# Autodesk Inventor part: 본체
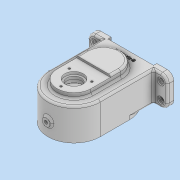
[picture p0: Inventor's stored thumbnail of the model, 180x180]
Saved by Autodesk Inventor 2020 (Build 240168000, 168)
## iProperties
Created: 2021-05
Part Number: 본체
Material: 일반
Document SubType Name: Modeling
Designer: Owner
Density: 1 g/cm^3
Appearance: 기본값
Mass: 280.11 g
Surface Area: 582.454 cm^2
Volume: 280.11 cm^3
Author: Owner
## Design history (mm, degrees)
sketch "스케치2"
  geometry: L1 (-61, 21.643)-(-35, 21.643); L2 (-35, 21.643)-(-35, -24.357); L3 (-35, -24.357)-(-61, -24.357); L4 (-61, -24.357)-(-61, 21.643); L5 (35, 21.643)-(61, 21.643); L6 (61, 21.643)-(61, -24.357); L7 (61, -24.357)-(35, -24.357); L8 (35, -24.357)-(35, 21.643); L9 (0, 30.578)-(0, 7.094); 1 further point
  constraints: 18 end point, 4 parallel, 2 horizontal, 2 perpendicular, 1 collinear, 1 point on line, 1 vertical, 2 other
  dimensions: "d2" = 46 distance of L1.end L2.end; "d3" = 46 distance of L7.end L5.start; "d4" = 122 distance between parallel lines of L6 L4; "d5" = 70 distance between parallel lines of L2 L8
extrude "돌출1" new body sketch "스케치2" distance "d6" = 10; taper "d7" = 0 deg
sketch "스케치3"
  geometry: L1 (-35, -92)-(-35, -47); L2 (5, -92)-(5, -47); L3 (-75, -47)-(-75, -92); L4 (-70, 0)-(-96, 0) reference; A1 r 40 centre (-35, -92) between (-75, -92) and (5, -92); A2 r 40 centre (-35, -47) between (5, -47) and (-75, -47); 2 further points
  constraints: 8 end point, 4 point on circle, 4 tangent, 2 centre point, 1 midpoint, 1 parallel, 1 vertical
  dimensions: "d8" = 80 distance between parallel lines of L2 L3; "d9" = 45 distance of L3.start L3.end; "d10" = 47 distance from line of L4 L3.start
extrude "돌출2" join sketch "스케치3" distance "d11" = 49; taper "d12" = 0 deg
sketch "스케치4"
  geometry: L1 (5, -92)-(5, -47) reference; L2 (5, -47)-(5, -10); L3 (0, -10)-(26, -10) reference; L4 (-75, -47)-(-75, -10); L5 (11.632, -5)-(-75, -5); L6 (26, 0)-(0, 0) reference; L7 (26, -10)-(0, -10) reference; L8 (0, 0)-(0, -10) reference; L9 (-70, 0)-(-70, -10) reference; L10 (-70, -10)-(-96, -10) reference; A1 r 40 centre (-35, -47) between (5, -47) and (-75, -47) reference; A2 r 40 centre (-35, -47) between (5, -47) and (-75, -47) reference; 3 further points
  constraints: 6 end point, 2 point on line, 2 vertical, 1 horizontal, 1 tangent
  dimensions: "d13" = 5 distance between parallel lines of L6 L5
extrude "돌출3" join sketch "스케치4" distance "d14" = 46; taper "d15" = 0 deg
sketch "스케치7"
  geometry: L1 (-35, 92)-(-35, 47); L2 (-65, 92)-(-65, 47); L3 (-5, 47)-(-5, 92); L4 (0, 0)-(26, 0) reference; A1 r 30 centre (-35, 92) between (-5, 92) and (-65, 92); A2 r 30 centre (-35, 47) between (-65, 47) and (-5, 47); 2 further points
  constraints: 8 end point, 4 point on circle, 4 tangent, 2 centre point, 1 midpoint, 1 parallel, 1 vertical, 1 vertical alignment
  dimensions: "d25" = 30 radius of A1; "d26" = 47 distance from line of L4 L1.end; "d27" = 45 distance of L1.end L1.start
extrude "돌출5" cut sketch "스케치7" distance "d28" = 41; taper "d29" = 0 deg
sketch "스케치8"
  geometry: L1 (61, -92)-(61, -47); L2 (87, -92)-(87, -47); L3 (35, -47)-(35, -92); L4 (122, 0)-(96, 0) reference; L5 (135.642, -62)-(-32.91, -62); A1 r 26 centre (61, -92) between (35, -92) and (87, -92); A2 r 26 centre (61, -47) between (87, -47) and (35, -47); 4 further points
  constraints: 10 end point, 4 point on circle, 4 tangent, 2 centre point, 1 horizontal, 1 midpoint, 1 parallel, 1 vertical, 1 vertical alignment
  dimensions: "d30" = 52 distance between parallel lines of L3 L2; "d31" = 47 distance from line of L4 L1.end; "d32" = 45 distance of L1.end L1.start; "d33" = 30 distance from line of L1.start L5
extrude "돌출6" join sketch "스케치8" distance "d34" = 8; taper "d35" = 0 deg
extrude "돌출7" join sketch "스케치8" distance "d36" = 11; taper "d37" = 0 deg
fillet "모깎기2" dims "d38" = 5
sketch "스케치10"
  geometry: L1 (26, 0)-(0, 0) reference; C1 r 14 at (61, -92); C2 r 11 at (61, -92); 1 further point
  constraints: 2 centre point, 1 coincident
  dimensions: "d46" = 28 diameter of C1; "d47" = 22 diameter of C2; "d48" = 92 distance from line of L1 C1.centre
extrude "돌출8" cut sketch "스케치10" distance "d49" = 4; taper "d50" = 0 deg
extrude "돌출9" cut sketch "스케치10" distance "d51" = 8; taper "d52" = 0 deg
sketch "스케치11"
  geometry: C1 r 14 at (0, 0); 1 further point
  constraints: 1 centre point
  dimensions: "d53" = 28 diameter of C1
extrude "돌출10" cut sketch "스케치11" extent not by distance; stored distance "d54" = 8; taper "d55" = 0 deg
sketch "스케치13"
  geometry: L1 (-55.627, 47)-(65.323, 47); L2 (-24.357, 0)-(21.643, 0) reference; L3 (13.643, 47)-(13.643, 92) reference; L4 (21.643, 61)-(21.643, 57); L5 (21.643, 57)-(25.643, 57); L6 (21.643, 47)-(32.643, 47) reference; L7 (21.643, 61)-(13.643, 61); L8 (25.643, 57)-(25.643, 47); 2 further points
  constraints: 10 end point, 2 horizontal, 2 point on line, 1 perpendicular, 1 vertical
  dimensions: "d59" = 47 distance between parallel lines of L2 L1; "d60" = 20 diameter of L5 L1; "d87" = 8 distance of L4.start L7.end; "d88" = 4 distance of L4.end L5.end
revolve "회전1" sketch "스케치13" stored, may be unused: angle "d63" = 90 deg
node "작업 평면1"
sketch "스케치14"
  geometry: L1 (-40, -27.357)-(40, -27.357) reference; C1 r 6 at (0, -6.357); 1 further point
  constraints: 1 centre point, 1 vertical alignment
  dimensions: "d66" = 21 distance from line of L1 C1.centre; "d67" = 12 diameter of C1
extrude "돌출11" join sketch "스케치14" stored distance "d68" = 8; taper "d69" = 0 deg
sketch "스케치15"
  geometry: 2 further points
hole "구멍1" sketch "스케치15" at (0, 0) diameter "d70" = 4.917; stored, may be unused: countersink angle "d74" = 90 deg, drill point angle "d76" = 118 deg; dims "d71" = 12, "d72" = 4, "d73" = 2, "d75" = 17.1
sketch "스케치16"
  geometry: L1 (-35, 92)-(-35, 47); L2 (0, 92)-(0, 47); L3 (-70, 47)-(-70, 92); L4 (0, 0)-(26, 0) reference; A1 r 35 centre (-35, 92) between (0, 92) and (-70, 92); A2 r 35 centre (-35, 47) between (-70, 47) and (0, 47); 8 further points
  constraints: 8 end point, 6 point on circle, 4 coincident, 4 tangent, 2 centre point, 1 midpoint, 1 parallel, 1 vertical
  dimensions: "d77" = 35 radius of A1; "d78" = 47 distance from line of L4 L1.end; "d79" = 45 distance of L1.end L1.start
hole "구멍2" sketch "스케치16" at (-70, 92), (-35, 127), (0, 92), (0, 47), (-35, 12), (-70, 47) diameter "d80" = 3.242; stored, may be unused: countersink angle "d84" = 90 deg, drill point angle "d86" = 118 deg; dims "d81" = 8, "d82" = 4, "d83" = 2, "d85" = 10
sketch "스케치17"
  geometry: L1 (-5, -49)-(75, -49) reference; 2 further points
  constraints: 1 vertical alignment
  dimensions: "d90" = 21 distance from line of L1 point (35, -28)
hole "구멍3" sketch "스케치17" at (35, -28) diameter "d91" = 4.917; stored, may be unused: countersink angle "d95" = 90 deg, drill point angle "d97" = 118 deg; dims "d92" = 12, "d93" = 12, "d94" = 1, "d96" = 17.1
sketch "스케치18"
  geometry: L1 (40, 21.643)-(40, -27.357) reference; L2 (10.022, -1.357)-(-26.327, -1.357); L3 (-35, -24.357)-(35, -24.357) reference; C1 r 5.5 at (51, -14.306); C2 r 5.5 at (51, 10.694); C3 r 3.3 at (51, -14.306); C4 r 3.3 at (51, 10.694); 1 further point
  constraints: 4 centre point, 2 coincident, 2 end point, 1 horizontal
  dimensions: "d117" = 11 diameter of C2; "d118" = 6.6 diameter of C4; "d119" = 11 diameter of C1; "d120" = 6.6 diameter of C3; "d123" = 11 distance from line of C1.centre L1; "d124" = 11 distance from line of L1 C2.centre; "d125" = 23 distance between parallel lines of L2 L3; "d128" = 25 distance of C2.centre C1.centre
fillet "모깎기5" dims "d98" = 3
fillet "모깎기6" dims "d99" = 3
fillet "모깎기7" dims "d100" = 3
sketch "스케치19"
  geometry: L1 (26, 0)-(0, 0) reference; A1 r 20 centre (61, -92) between (61, -112) and (43.679, -82); 2 further points
  constraints: 3 point on circle, 2 vertical alignment, 1 centre point
  dimensions: "d101" = 92 distance from line of A1.centre L1; "d102" = 40 diameter of A1; "d103" = 120 deg dimension on A1.centre A1.end A1.start; "d104" = 120 deg dimension on A1.centre point (78.321, -82) A1.start
hole "구멍4" sketch "스케치19" at (43.679, -82), (61, -112), (78.321, -82) diameter "d105" = 3.242; stored, may be unused: countersink angle "d109" = 90 deg, drill point angle "d111" = 118 deg; dims "d106" = 8, "d107" = 4, "d108" = 2, "d110" = 10
fillet "모깎기8" dims "d112" = 0.3
fillet "모깎기9" dims "d113" = 3
chamfer "모따기1" distance "d114" = 1; stored, may be unused: second distance "d115" = 2, angle "d116" = 45 deg
fillet "모깎기11" dims "d122" = 10
extrude "돌출12" cut sketch "스케치18" distance "d129" = 2; taper "d130" = 0 deg
extrude "돌출13" cut sketch "스케치18" extent not by distance; stored distance "d131" = 0; taper "d132" = 0 deg
fillet "모깎기12" dims "d133" = 3
sketch "스케치20"
  geometry: L1 (116.207, -7)-(-46.207, -7); L2 (86, 5)-(70, 5) reference; L3 (35, -42.797)-(35, 22.66); 1 further point
  constraints: 4 end point, 2 horizontal, 1 symmetric about line, 1 vertical
  dimensions: "d134" = 12 distance between parallel lines of L2 L1
extrude "돌출14" join sketch "스케치20" distance "d135" = 0.5; taper "d136" = 0 deg
node "솔리드1"
mirror "미러1"
feature "A9D066F2-1C7D-4E18-AEED-F7BC21143FA4" dims "d80" = 3.242, "d81" = 8, "d82" = 4, "d83" = 2, "d84" = 90 deg, "d85" = 10, "d86" = 118 deg
other parameters: "d65" = -135
